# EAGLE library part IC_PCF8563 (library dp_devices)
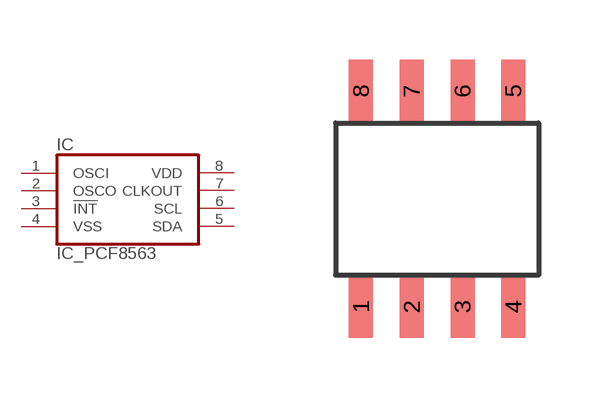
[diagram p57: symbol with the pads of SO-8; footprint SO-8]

Designator prefix IC

## IC_PCF8563  [SO-8]
1  OSCI
2  OSCO
3  !INT
4  VSS
5  SDA
6  SCL
7  CLKOUT
8  VDD

## Footprint SO-8 (pad centres in mm)
smd 0.6 x 1.55: 1 -1.905,-2.69; 2 -0.635,-2.69; 3 0.635,-2.69; 4 1.905,-2.69; 5 1.905,2.71; 6 0.635,2.71; 7 -0.635,2.71; 8 -1.905,2.71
